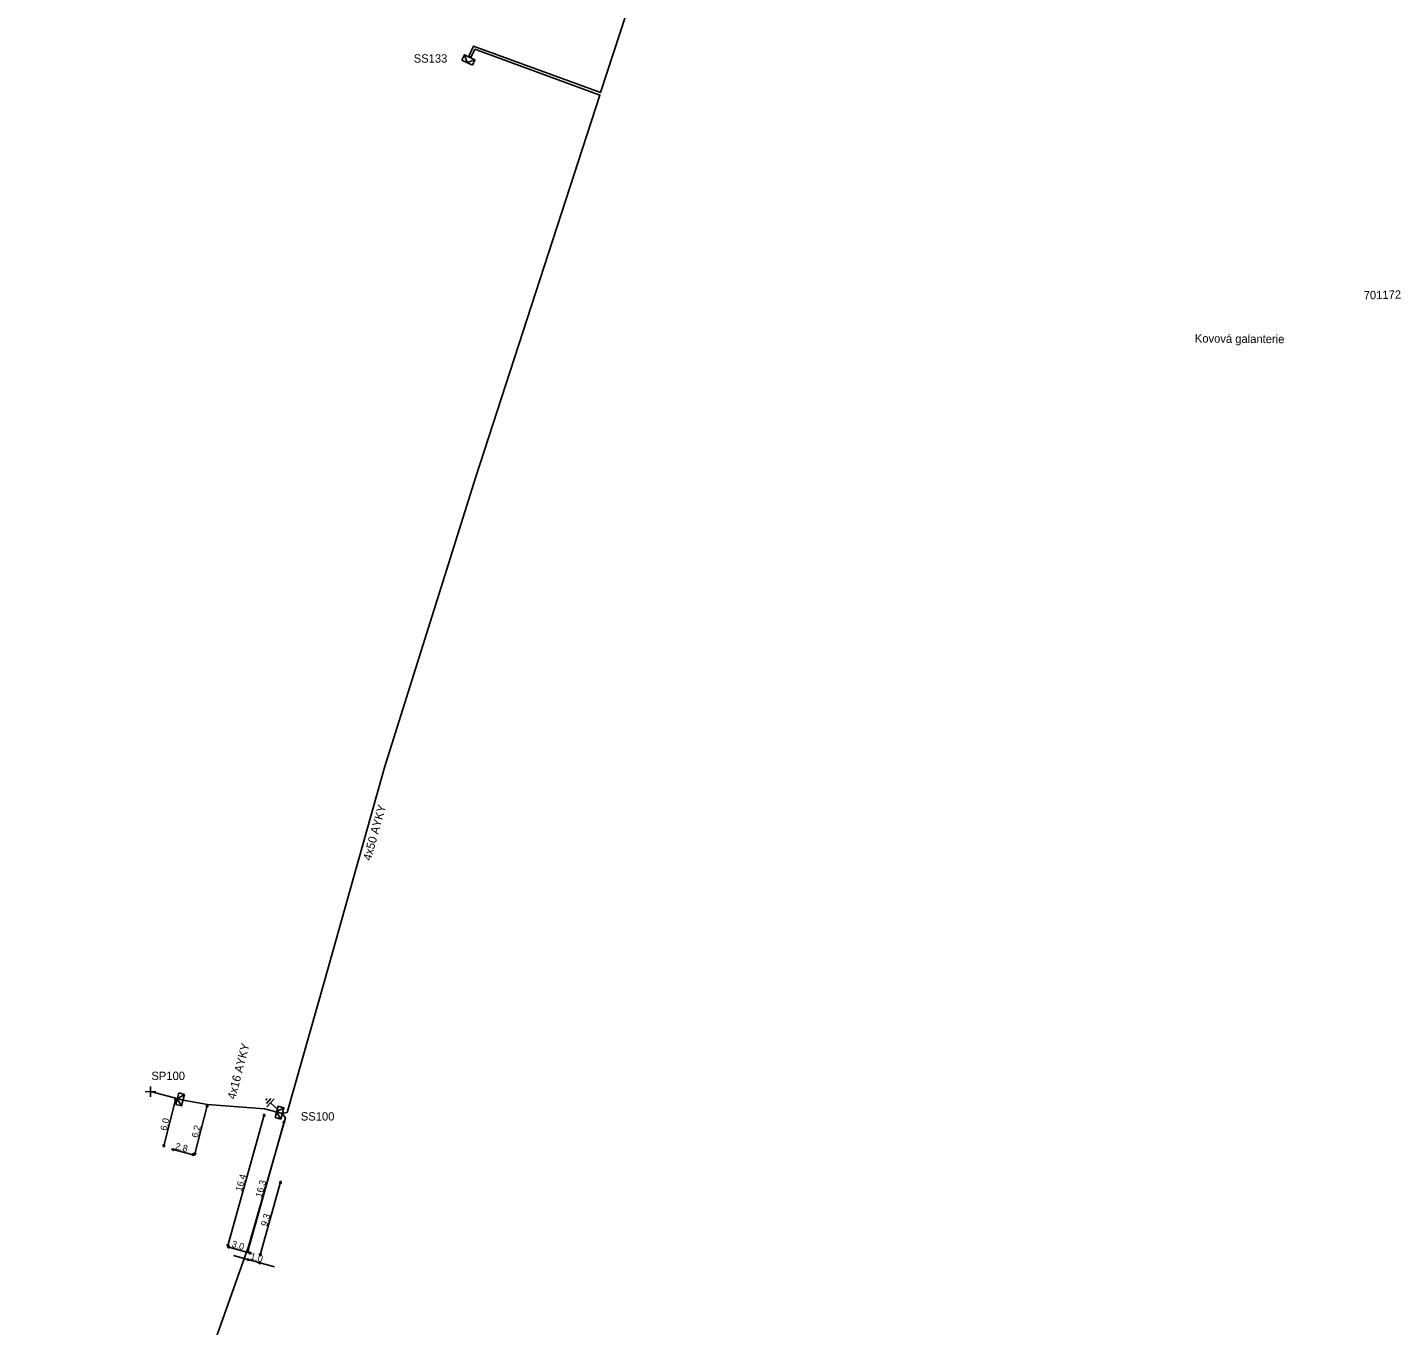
# Model space of a CAD drawing. Extents: x -762500 to -761285, y -1155006 to -1154135.
# Drawn here: x -761896.1 to -761732.9, y -1154443.6 to -1154289.3 of the extents above; entities that cross this region are included whole.
import ezdxf

# ---------------------------------------------------------------- set-up
doc = ezdxf.new("R2010")
doc.units = 0
for name, color, linetype in [('Vrstva 15', 7, 'Continuous'), ('Vrstva 26', 7, 'Continuous'), ('Vrstva 27', 7, 'Continuous'), ('Vrstva 31', 7, 'Continuous'), ('Vrstva 33', 7, 'Continuous'), ('Vrstva 34', 7, 'Continuous'), ('Vrstva 40', 7, 'Continuous'), ('Vrstva 5', 7, 'Continuous'), ('Vrstva 59', 7, 'Continuous'), ('Vrstva 6', 7, 'Continuous')]:
    doc.layers.add(name, color=color, linetype=linetype)

msp = doc.modelspace()

# ---------------------------------------------------------------- linework, layer by layer
at = {"layer": 'Vrstva 15'}
for points in [[(-761867.721, -1154416.829), (-761867.632, -1154416.73)], [(-761867.654, -1154417.226), (-761867.128, -1154416.641)], [(-761867.632, -1154416.73), (-761867.546, -1154416.635)], [(-761867.585, -1154417.613), (-761866.749, -1154416.684)], [(-761866.238, -1154417.985), (-761867.167, -1154417.149)]]:
    msp.add_lwpolyline(points, dxfattribs=at)
at = {"layer": 'Vrstva 31'}
for points in [[(-761844.428, -1154293.201), (-761844.122, -1154292.572), (-761842.863, -1154293.186), (-761843.17, -1154293.815)], [(-761844.428, -1154293.201), (-761843.17, -1154293.815)], [(-761843.799, -1154293.508), (-761844.122, -1154292.572)], [(-761843.799, -1154293.508), (-761842.863, -1154293.186)], [(-761878.07, -1154415.979), (-761878.409, -1154417.337)], [(-761878.07, -1154415.979), (-761877.391, -1154416.148), (-761877.73, -1154417.506), (-761878.409, -1154417.337)], [(-761878.239, -1154416.658), (-761877.391, -1154416.148)], [(-761878.239, -1154416.658), (-761877.73, -1154417.506)], [(-761866.24, -1154417.541), (-761866.626, -1154418.887)], [(-761866.24, -1154417.541), (-761865.567, -1154417.734), (-761865.953, -1154419.08), (-761866.626, -1154418.887)], [(-761866.433, -1154418.214), (-761865.567, -1154417.734)], [(-761866.433, -1154418.214), (-761865.953, -1154419.08)]]:
    msp.add_lwpolyline(points, dxfattribs=at)
at = {"layer": 'Vrstva 34'}
for points in [[(-761882.055, -1154415.831), (-761880.805, -1154415.809)], [(-761881.419, -1154416.445), (-761881.441, -1154415.195)]]:
    msp.add_lwpolyline(points, dxfattribs=at)
at = {"layer": 'Vrstva 40'}
for points in [[(-761879.89, -1154422.43), (-761878.4, -1154416.62)], [(-761876.2, -1154423.37), (-761874.66, -1154417.37)], [(-761872.29, -1154434.28), (-761867.87, -1154418.47)], [(-761865.52, -1154419.24), (-761869.91, -1154434.95)], [(-761876.19, -1154423.36), (-761878.91, -1154422.67)], [(-761868.42, -1154435.37), (-761865.92, -1154426.44)], [(-761869.41, -1154435.07), (-761872.29, -1154434.26)], [(-761871.56, -1154435.31), (-761866.7, -1154436.65)]]:
    msp.add_lwpolyline(points, dxfattribs=at)
for points in [[(-761878.399, -1154416.618), (-761878.358, -1154416.884), (-761878.561, -1154416.834)], [(-761874.659, -1154417.368), (-761874.618, -1154417.634), (-761874.821, -1154417.584)], [(-761867.869, -1154418.467), (-761867.832, -1154418.735), (-761868.034, -1154418.68)], [(-761865.519, -1154419.238), (-761865.483, -1154419.505), (-761865.685, -1154419.451)], [(-761879.891, -1154422.433), (-761879.932, -1154422.166), (-761879.729, -1154422.217)], [(-761878.912, -1154422.67), (-761878.646, -1154422.628), (-761878.696, -1154422.831)], [(-761876.188, -1154423.361), (-761876.454, -1154423.402), (-761876.404, -1154423.2)], [(-761876.201, -1154423.372), (-761876.242, -1154423.106), (-761876.039, -1154423.156)], [(-761865.919, -1154426.438), (-761865.883, -1154426.705), (-761866.084, -1154426.651)], [(-761872.29, -1154434.282), (-761872.327, -1154434.015), (-761872.125, -1154434.069)], [(-761872.293, -1154434.259), (-761872.026, -1154434.222), (-761872.08, -1154434.424)], [(-761869.911, -1154434.952), (-761869.948, -1154434.685), (-761869.746, -1154434.739)], [(-761869.408, -1154435.071), (-761869.675, -1154435.107), (-761869.621, -1154434.905)], [(-761868.421, -1154435.372), (-761868.457, -1154435.105), (-761868.256, -1154435.159)], [(-761869.627, -1154435.841), (-761869.895, -1154435.877), (-761869.84, -1154435.676)], [(-761868.632, -1154436.119), (-761868.365, -1154436.083), (-761868.419, -1154436.284)]]:
    msp.add_lwpolyline(points, close=True, dxfattribs=at)
at = {"layer": 'Vrstva 5'}
for points in [[(-761865.76, -1154418.41), (-761865.2, -1154418.3), (-761860.7, -1154402.52), (-761853.63, -1154377.31), (-761842.77, -1154342.76), (-761828.01, -1154297.38), (-761842.58, -1154292.02), (-761842.88, -1154291.91), (-761843.3, -1154292.83), (-761843.49, -1154292.88), (-761843.56, -1154292.67), (-761843.04, -1154291.54), (-761827.94, -1154297.08), (-761803.61, -1154222.76), (-761800.64, -1154214.04), (-761786.13, -1154207.56), (-761785.73, -1154207.67)], [(-761877.56, -1154416.83), (-761874.66, -1154417.37), (-761867.86, -1154417.86), (-761865.76, -1154418.41)], [(-761895.51, -1154530.78), (-761895.62, -1154530.65), (-761896.05, -1154530.41), (-761894.54, -1154524.27), (-761894.15, -1154523.62), (-761892.39, -1154516.56), (-761882.4, -1154477.51), (-761875.49, -1154450.3), (-761869.77, -1154434.24), (-761865.39, -1154418.93), (-761865.76, -1154418.41)]]:
    msp.add_lwpolyline(points, dxfattribs=at)
at = {"layer": 'Vrstva 59'}
msp.add_lwpolyline([(-761877.56, -1154416.83), (-761881.43, -1154415.82)], dxfattribs=at)

# ---------------------------------------------------------------- texts
at = {"layer": 'Vrstva 26'}
msp.add_text('701172', height=0.9943, rotation=1.23607, dxfattribs=at).set_placement((-761737.23, -1154321.66))
at = {"layer": 'Vrstva 27'}
msp.add_text('Kovová galanterie', height=0.99429, rotation=359.54484, dxfattribs=at).set_placement((-761757.31, -1154326.78))
at = {"layer": 'Vrstva 33'}
for s, p in [('SS133', (-761850.14, -1154293.51)), ('SP100', (-761881.32, -1154414.44)), ('SS100', (-761863.56, -1154419.26))]:
    msp.add_text(s, height=0.9943, dxfattribs=at).set_placement(p)
at = {"layer": 'Vrstva 40'}
for s, rotation, p in [('6,0', 75.68661, (-761879.52, -1154420.52)), ('6,2', 75.6499, (-761875.81, -1154421.37)), ('2,8', 345.65546, (-761878.55, -1154422.64)), ('16,4', 74.35811, (-761870.59, -1154427.75)), ('16,3', 74.3895, (-761868.22, -1154428.47)), ('9,3', 74.35966, (-761867.57, -1154431.89)), ('3,0', 344.35747, (-761871.84, -1154434.26)), ('1,0', 344.58765, (-761869.62, -1154435.72))]:
    msp.add_text(s, height=0.7954, rotation=rotation, dxfattribs=at).set_placement(p)
at = {"layer": 'Vrstva 6'}
for s, rotation, p in [('4x50 AYKY', 74.34073, (-761855.25, -1154388.43)), ('4x16 AYKY', 75.36936, (-761871.36, -1154416.8))]:
    msp.add_text(s, height=0.9943, rotation=rotation, dxfattribs=at).set_placement(p)

doc.saveas('drawing.dxf')
